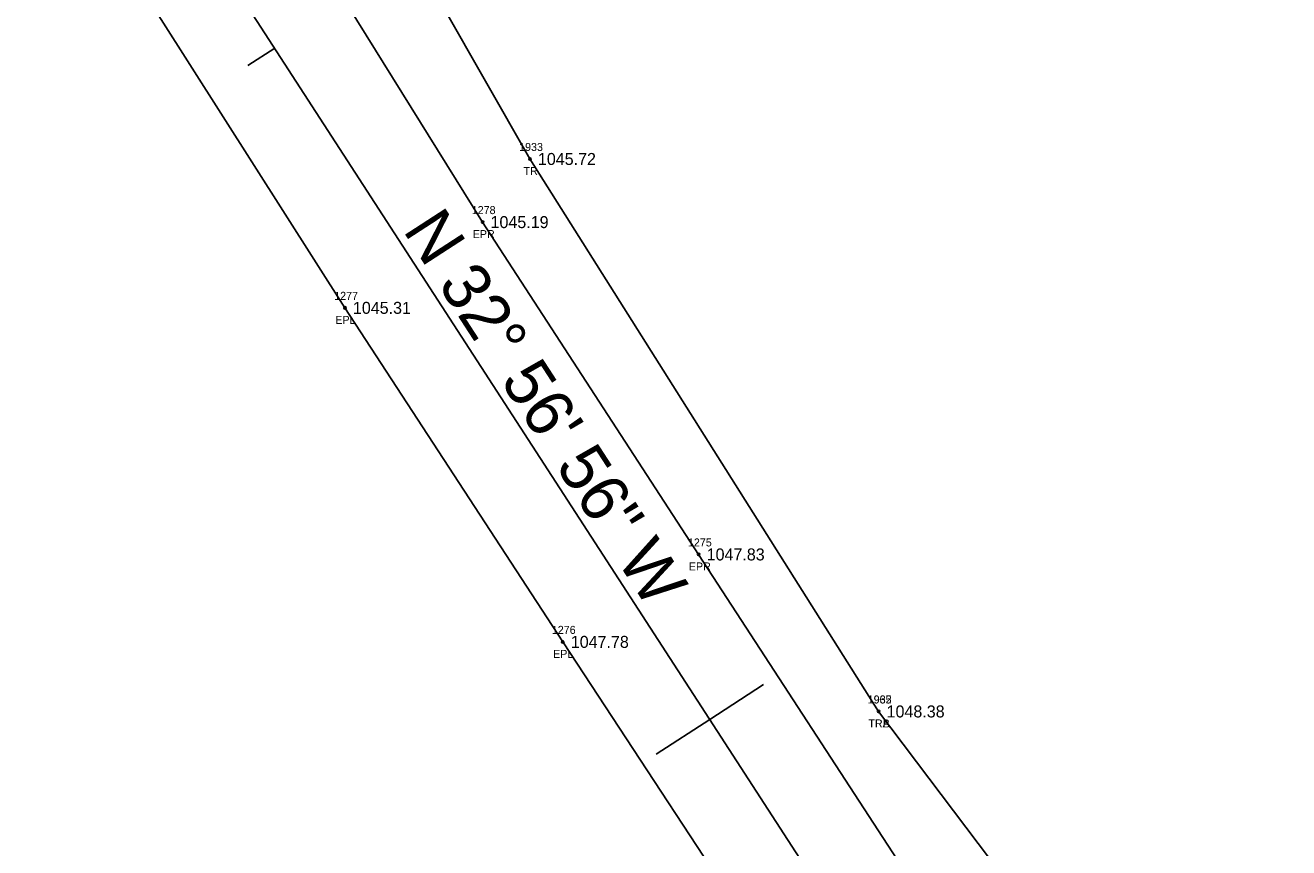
# Model space of a CAD drawing. Extents: x 1578957 to 1581675, y 1115963 to 1120391.
# Drawn here: x 1580170.3 to 1580328.3, y 1116868.5 to 1116971.4 of the extents above; entities that cross this region are included whole.
import ezdxf

# ---------------------------------------------------------------- set-up
doc = ezdxf.new("R2010")
doc.units = 0
for name, color, linetype in [('RD_EX_Road', 7, 'Continuous'), ('RD_EX_Road_txCode', 7, 'Continuous'), ('RD_EX_TX_Road_ELEV', 7, 'Continuous'), ('RD_EX_TX_VEG_ELEV', 7, 'Continuous'), ('RD_EX_VEG', 7, 'Continuous'), ('RD_EX_VEG_txCode', 7, 'Continuous'), ('RD_HC_Cl', 7, 'Continuous'), ('RD_HC_Data', 7, 'Continuous'), ('RD_HC_Data_Tic', 7, 'Continuous'), ('RD_SMD_Locator', 7, 'Continuous')]:
    doc.layers.add(name, color=color, linetype=linetype)

msp = doc.modelspace()

# ---------------------------------------------------------------- linework, layer by layer
at = {"layer": 'RD_EX_Road'}
for points in [[(1580570.71, 1116498.67), (1580529.36, 1116480.65), (1580519.91, 1116479.43), (1580510.64, 1116479.83), (1580504.14, 1116481.67), (1580497.17, 1116485.13), (1580490.27, 1116490.58), (1580483.83, 1116498.29), (1580485.04, 1116499.02), (1580478.37, 1116510.01), (1580451.15, 1116557.41), (1580425.99, 1116599.55), (1580403.29, 1116644.83), (1580382.32, 1116688.41), (1580373.95, 1116705.15), (1580352.79, 1116744.5), (1580332.46, 1116780.72), (1580308.51, 1116820.53), (1580282.29, 1116862.52), (1580254.51, 1116905.2), (1580227.5, 1116946.75), (1580201.69, 1116988.26)], [(1580373.02, 1116418.01), (1580425.37, 1116439.24), (1580432.48, 1116444.21), (1580439.18, 1116451.49), (1580444.63, 1116463.6), (1580445.94, 1116475), (1580444.74, 1116484.46), (1580443.03, 1116489.18), (1580441.49, 1116488.99), (1580438.54, 1116496.4), (1580426.11, 1116533.96), (1580423.22, 1116543.6), (1580405.6, 1116590.01), (1580384.87, 1116635.19), (1580363.63, 1116679.91), (1580314.77, 1116769.46), (1580304.81, 1116786.68), (1580291.3, 1116810.33), (1580264.82, 1116852.68), (1580237.53, 1116894.27), (1580210.3, 1116936.03), (1580183.44, 1116978.21)]]:
    msp.add_lwpolyline(points, dxfattribs=at)
at = {"layer": 'RD_EX_VEG'}
for points in [[(1580277, 1116885.57), (1580233.42, 1116954.64), (1580211.73, 1116992.65), (1580162.48, 1117078.36), (1580126.56, 1117167.16), (1580096.12, 1117258.64), (1580083.87, 1117306.88), (1580091.45, 1117332.17)], [(1580391.81, 1116828.04), (1580364.95, 1116813.73), (1580356.71, 1116779.91), (1580277, 1116885.57)]]:
    msp.add_lwpolyline(points, dxfattribs=at)
at = {"layer": 'RD_HC_Cl'}
msp.add_line((1580269.83, 1116863.1), (1580195.86, 1116977.22), dxfattribs=at)
at = {"layer": 'RD_HC_Data_Tic'}
for p, q in [((1580201.52, 1116968.49), (1580198.16, 1116966.32)), ((1580255.91, 1116884.58), (1580262.62, 1116888.93)), ((1580255.91, 1116884.58), (1580249.19, 1116880.23))]:
    msp.add_line(p, q, dxfattribs=at)
at = {"layer": 'RD_SMD_Locator'}
for centre in [(1580233.42, 1116954.64), (1580227.5, 1116946.75), (1580210.3, 1116936.03), (1580254.51, 1116905.2), (1580237.53, 1116894.27), (1580277, 1116885.57), (1580277, 1116885.57)]:
    msp.add_circle(centre, 0.15, dxfattribs=at)

# ---------------------------------------------------------------- texts
at = {"layer": 'RD_EX_Road_txCode'}
for s, p in [('1278', (1580226.15, 1116947.75)), ('EPR', (1580226.27, 1116944.75)), ('1277', (1580208.96, 1116937.03)), ('EPL', (1580209.1, 1116934.03)), ('1275', (1580253.17, 1116906.2)), ('EPR', (1580253.28, 1116903.2)), ('1276', (1580236.16, 1116895.27)), ('EPL', (1580236.32, 1116892.27))]:
    msp.add_text(s, height=1, dxfattribs=at).set_placement(p)
at = {"layer": 'RD_EX_TX_Road_ELEV'}
for s, p in [('1045.19', (1580228.5, 1116946)), ('1045.31', (1580211.3, 1116935.28)), ('1047.83', (1580255.51, 1116904.45)), ('1047.78', (1580238.53, 1116893.52))]:
    msp.add_text(s, height=1.5, dxfattribs=at).set_placement(p)
at = {"layer": 'RD_EX_TX_VEG_ELEV'}
for s, p in [('1045.72', (1580234.42, 1116953.89)), ('1048.38', (1580278, 1116884.82)), ('1048.38', (1580278, 1116884.82))]:
    msp.add_text(s, height=1.5, dxfattribs=at).set_placement(p)
at = {"layer": 'RD_EX_VEG_txCode'}
for s, p in [('1933', (1580232.07, 1116955.64)), ('TR', (1580232.62, 1116952.64)), ('1965', (1580275.63, 1116886.57)), ('1932', (1580275.65, 1116886.57)), ('TRA', (1580275.71, 1116883.57)), ('TRB', (1580275.73, 1116883.57))]:
    msp.add_text(s, height=1, dxfattribs=at).set_placement(p)
at = {"layer": 'RD_HC_Data'}
msp.add_text('N 32%%d 56\' 56" W', height=6, rotation=302.9489, dxfattribs=at).set_placement((1580217.46, 1116945.74))

doc.saveas('drawing.dxf')
